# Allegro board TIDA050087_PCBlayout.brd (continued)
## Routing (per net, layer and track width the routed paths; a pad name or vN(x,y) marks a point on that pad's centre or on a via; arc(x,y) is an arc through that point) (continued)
LVDS_TX1_N: length 28.3
  TOP w0.081: 49.6,46.87 49.61,46.86 49.61,46.86 49.67,46.81 49.67,46.8 49.75,46.72 49.75,44.59 49.19,44.04 49.19,43.72 U101.A4
  TOP w0.086: v1(47.04,60.36) 47.16,60.36 47.84,59.68 47.84,58.24 46.02,56.42 43,56.42 42.18,55.6 42.18,51.54 43.04,50.68 45.79,50.68 49.6,46.87
  BOTTOM w0.086: v1(47.04,60.36) 47.09,60.36 47.88,59.57 J802.24
LVDS_TX1_P: length 28.1
  TOP w0.081: U101.B4 48.97,43.45 48.97,44.13 49.53,44.68 49.53,46.63 49.44,46.71
  TOP w0.086: 49.44,46.71 45.7,50.45 42.94,50.45 41.95,51.44 41.95,55.7 42.9,56.65 45.93,56.65 47.62,58.34 47.62,58.56 47.38,58.8 47.38,59.07 47.62,59.31 47.62,59.58 47.28,59.92 47.16,59.92 v1(47.07,59.83)
  BOTTOM w0.086: v1(47.07,59.83) 47.3,59.83 47.65,59.47 47.65,59.1 47.48,58.93 J802.22
LVDS_TX2_N: length 28
  TOP w0.081: U101.A2 48.22,44.03 48.06,44.19 48.06,44.19 48.05,44.2
  TOP w0.086: 48.05,44.2 47.69,44.57 47.69,45.89 48.01,46.21 48.01,46.7 45.43,49.27 42.28,49.27 40.89,50.66 40.89,57.19 41.43,57.73 44.97,57.73 45.32,58.09 45.32,59.74 v1(44.7,60.36)
  BOTTOM w0.086: v1(44.7,60.36) 45.48,59.58 J802.12
LVDS_TX2_P: length 28
  TOP w0.081: 47.89,44.04 47.97,43.96 47.97,43.45 U101.B2
  TOP w0.086: 47.89,44.04 47.46,44.47 47.46,45.98 47.78,46.3 47.78,46.6 45.34,49.04 42.18,49.04 40.66,50.57 40.66,57.28 41.34,57.96 44.87,57.96 45.1,58.18 45.1,58.55 44.84,58.8 44.84,58.93 45.1,59.18 45.1,59.64 44.91,59.83 v1(44.67,59.83)
  BOTTOM w0.086: v1(44.67,59.83) 44.91,59.83 45.25,59.49 45.25,59.1 45.08,58.93 J802.10
LVDS_TX3_N: length 28
  TOP w0.081: 46.66,46.62 47.21,46.08 47.21,44.42 46.97,44.18 46.97,43.94 47.56,43.34 47.58,43.34 U101.B1
  TOP w0.086: 46.66,46.62 46.66,47.13 45.17,48.63 41.98,48.63 40.21,50.4 40.21,57.46 41.12,58.38 43.73,58.38 44.22,58.86 44.22,59.62 43.52,60.32 43.51,60.32 v1(43.45,60.38)
  BOTTOM w0.086: v1(43.45,60.38) 43.46,60.38 44.28,59.56 J802.6
LVDS_TX3_P: length 27.9
  TOP w0.081: U101.C1 47.34,43.08 47.34,43.25 46.75,43.84 46.75,44.28 46.98,44.52 46.98,45.98 46.57,46.4 46.57,46.4 46.52,46.45 46.43,46.53 46.43,46.6 46.43,46.61 46.43,46.62
  TOP w0.086: v1(43.49,59.83) 43.68,59.83 43.68,59.83 43.99,59.53 43.99,58.96 43.64,58.61 43.52,58.61 43.29,58.84 43.17,58.84 42.93,58.61 42.81,58.61 42.58,58.84 42.46,58.84 42.22,58.6 41.03,58.6 39.98,57.56 39.98,50.3 41.89,48.4 45.07,48.4 46.43,47.04 46.43,46.62
  BOTTOM w0.086: v1(43.49,59.83) 43.69,59.83 44.05,59.47 44.05,59.11 43.88,58.94 J802.4
M1_SCL: length 1.5
  TOP w0.203: R906.1 2.77,39.49 U902.4
M1_SDA: length 2.1
  TOP w0.254: U902.5 5.23,38.23 4.34,37.33 R910.1
M2_SCL: length 1.5
  TOP w0.203: R926.1 2.86,52.51 U904.4
M2_SDA: length 2.2
  TOP w0.254: U904.5 5.13,50.55 R928.1
M3_SCL: length 1.4
  TOP w0.254: U907.4 17.29,39.29 R946.1
M3_SDA: length 2.2
  TOP w0.254: R948.1 18.34,37.98 U907.5
M4_SCL: length 1.7
  TOP w0.254: R988.1 3.09,26.53 U911.4
M5_SCL: length 1.5
  TOP w0.254: R1019.1 3.62,13.07 3.64,13.08 U912.4
M5_SDA: length 2.4
  TOP w0.254: U912.5 5.48,11.45 4.61,10.58 R1021.1
MX_POR_B: length 13.4
  TOP w0.112: v1(56.3,54.13) 56.38,54.05 TP408.1 56.39,53.11 56.39,45.58 55.24,44.43 55.24,43.71 U101.A16
  BOTTOM w0.112: v1(56.3,54.13) 56.3,54.08 55.84,53.62 R404.2 55.84,53.59 C405.1 54.72,53.61 R406.2
NVCC_1P8: length 13.7
  TOP w0.203: R106.1 14.08,8.19 14.08,9.27 13.22,10.12 13.22,12.01 12.83,12.4 12.15,12.4 R1029.1 ; U101.W8 50.81,34.7 v1(50.74,34.63) ; U101.R12 52.73,36.7 52.72,36.69 v1(52.72,36.69) 52.71,36.7 U101.R10
  TOP w0.381: v1(12.63,7.01) 13.2,7.01 13.47,6.74 13.53,6.8 13.53,7.62 13.95,8.04 R106.1 ; v1(46.27,28.64) v1(46.27,25.86)
  BOTTOM w0.254: C116.1 50.75,34.62 v1(50.74,34.63) ; v1(52.72,36.69) 52.77,36.63 C117.1
  vias: v1(12.41,33.78) v1(12.41,33.14) v1(12.62,7.54) v1(12.66,8.11) v1(16.28,33.78) v1(16.32,33.25)
NVCC_3P3: length 121.4
  TOP w0.203: R989.1 v1(7.35,32.59)
  TOP w0.381: 40.87,3.61 40.87,3.49 43.66,0.7 64.81,0.7 68.35,4.24 68.35,15.28 70.83,17.75 70.83,24.81 70.42,25.22 69.12,25.22 68.82,25.52 R112.2 68.13,25.82 68.13,25.81 R113.2
  L3_INT_1 w0.203: v1(7.35,32.59) 7.35,32.11 8.41,31.05 8.41,26.31 6.64,24.53 6.64,17.61 8.31,15.93 8.31,11.39 6.58,9.66 6.58,7.41 8.42,5.57 10.46,5.57 14.42,1.6 38.09,1.6 39.41,2.92 39.99,2.92 40.19,3.12 v1(40.19,3.79)
NVCC_AON: length 58.5
  TOP w0.254: TP608.1 61.64,43.19 v1(62.4,43.95) 62.4,43.96 62.84,44.4 R601.1 ; U101.L16 55.22,38.23 v1(55.2,38.2) ; R602.1 67.16,44.41 67.48,44.09 68.82,44.09 R603.1 70.43,43.54 R604.1 70.45,44.23 70.92,44.7 71.92,44.7 72.32,44.3 72.32,28.42 70.55,26.64 C804.1 69.58,25.82 R112.1
  TOP w0.305: v1(68.34,48.25) R309.1 69.4,47.51 R308.1 70.63,47.51 R306.1 71.69,47.52 R307.1 71.96,47.54 72.27,47.23 72.27,45.04 71.92,44.7
  TOP w0.381: R112.1 70.15,25.82 v1(70.18,25.84)
  L3_INT_1 w0.305: v1(68.34,48.25) 68.34,46.79 66.59,45.04 63.49,45.04 v1(62.4,43.95)
  BOTTOM w0.254: J803.90 v1(70.18,25.84) ; v1(55.2,38.2) 55.2,37.97 55.46,37.7 57.08,37.7 C119.1 57.88,37.87 61.51,41.5 61.51,43.06 v1(62.4,43.95)
NVCC_BBSM_1P8: length 157.2
  TOP w0.112: v1(19.74,16.16) 19.33,16.16 R101.2
  TOP w0.203: v1(12.1,41.63) 11.92,41.63 R903.1 ; R918.1 11.84,38.93 v1(12.12,38.93) ; v1(53.71,40.68) 53.69,40.7 U101.G12
  L3_INT_1 w0.508: v1(17.28,12.81) 12.63,17.46 12.63,26.45 13.14,26.96 13.14,54.03 13.8,54.69 18.52,54.69 19.79,53.43 v3(19.79,53.35)
  BOTTOM w0.203: v1(17.28,12.81) 17.07,12.81 16.62,13.26 16.62,15.91 10.6,21.93 10.6,38.26 11.35,39.02 12.03,39.02 v1(12.12,38.93) ; C101.1 53.26,40.88 53.36,40.98 53.36,43.06 ; v1(12.1,41.63) 12.16,41.63 12.91,40.88 12.91,38.08 11.57,36.74 11.57,23.3 14.71,20.15 17.13,20.15 20.2,17.08 20.2,16.52 19.84,16.16 v1(19.74,16.16)
  BOTTOM w0.254: v1(53.71,40.68) 53.69,40.69 C101.1
  BOTTOM w0.305: 53.32,43.33 53.36,43.28 53.36,43.06
  BOTTOM w0.508: 53.32,43.33 53.32,43.6 53.33,43.61 53.33,44.54 53.32,44.55 53.32,45.38 48.79,49.92 24.95,49.92 22.35,52.51 20.63,52.51 v3(19.79,53.35)
NVCC_BBSM_1V8: length 101.8
  TOP w0.203: R902.1 11.73,41.08 v1(12.1,41.08)
  TOP w0.381: v1(27.64,56.39) 27.9,56.13 R971.1 ; Q901.1 v1(28.13,58.28)
  L3_INT_1 w0.381: v1(53.64,52.17) 53.09,52.17 52.49,52.76 v1(52.49,52.87)
  BOTTOM w0.203: v1(19.61,18.4) 19.61,19.73 21.52,21.64 R1096.1 R1097.1 25.67,21.64 27.67,19.64 30.24,19.64 30.7,20.1 R1064.1 30.7,21.08 31.01,21.39 32.61,21.39 34.03,19.97 35.64,19.97 38.49,17.13 38.49,15.53 35.06,12.1 34.16,12.1 R1102.1 33.91,11.39 33.63,11.11 31.1,11.11 30.06,10.07 R703.1 ; J802.53 53.88,54.78 C809.1 ; v1(19.77,16.72) 19.77,17 16.95,19.82 14.58,19.82 11.24,23.16 11.24,36.88 12.56,38.21 12.56,40.76 12.24,41.08 v1(12.1,41.08)
  BOTTOM w0.254: C809.1 53.53,54.72 53.17,54.37 53.17,54.13 52.49,53.45 v1(52.49,52.87)
  BOTTOM w0.381: R405.1 57.99,52.83 57.98,52.85 R401.1 56.38,52.85 56.37,52.84 R404.1 55.17,52.17 v1(53.64,52.17) 52.49,51.02 34.3,51.02 v1(34,50.72)
NVCC_BBSM_PULL UP: length 5.9
  TOP w0.127: v1(27.31,13.42) 27.37,13.48 U701.28
  BOTTOM w0.203: R703.2 28.65,10.76 R706.1 27.31,11.37 v1(27.31,13.42)
NVCC_GPIO: length 21.6
  TOP w0.254: v1(55.18,37.22) 55.22,37.27 U101.N16 U101.N15
  TOP w0.305: v1(65.92,25.92) 65.92,26.04 65.73,26.23 C806.1
  TOP w0.381: R113.1 66.15,25.81 66.05,25.92 v1(65.92,25.92)
  BOTTOM w0.254: v1(65.92,25.92) 66.25,25.92 66.32,25.84 66.8,25.84 ; C118.1 55.44,36.7 55.18,36.97 v1(55.18,37.22)
  BOTTOM w0.381: 64.62,25.84 64.69,25.92 v1(65.92,25.92) ; 64.61,25.83 62.55,27.88 62.55,32.26 58.12,36.7 C118.1
NVCC_SD: length 50.6
  TOP w0.203: R929.1 7.5,47.87 9.48,47.87 12.89,44.46 12.89,37.67 11.31,36.08 11.31,31.86 13.29,29.88 13.29,27.12 16.44,23.97 21.15,23.97 22.36,25.18 25.33,25.18 25.86,24.65 25.86,24.29 25.9,24.29
  TOP w0.254: 30.1,18.73 29.85,18.47 U701.7
  TOP w0.305: v1(32.19,22.59) 32.19,22.28 32.52,21.95 TP713.1 32.16,21.5 31.17,21.5 30.62,20.94 C731.1 30.62,20.2 30.75,20.07 30.75,19.37 30.1,18.73
  L3_INT_1 w0.381: v1(29.22,23.68) 31.1,23.68 v1(32.19,22.59)
NVCC_SD2: length 109.1
  TOP w0.203: 24.6,24.29 24.64,24.33 24.57,24.41 24.55,24.41 24.11,24.85 22.54,24.85 21.33,23.64 16.3,23.64 12.96,26.98 12.96,29.74 10.98,31.73 10.98,36.22 12.56,37.8 12.56,44.32 9.34,47.54 6.75,47.54 R935.1
  TOP w0.254: U101.R16 v1(54.73,36.7)
  TOP w0.457: R312.1 60.74,28.29 v1(60.77,28.32) ; v1(24.06,23.12) R108.1
  L3_INT_1 w0.457: v1(67.82,31.66) 66.98,32.5 63.09,32.5 v1(61.9,31.3) ; v1(44.41,23.93) 40.19,23.93 39.33,23.08 v1(37.25,23.08)
  BOTTOM w0.254: v1(67.82,31.66) 67.82,32.13 67.3,32.64 J803.55 ; C129.1 55.23,34.29 55.23,36.39 54.93,36.7 v1(54.73,36.7)
  BOTTOM w0.305: C129.1 55.32,33.55 56.78,32.08 56.78,30.32 58.78,28.32 v1(60.77,28.32)
  BOTTOM w0.457: v1(37.25,23.08) 36.22,22.05 33.91,22.05 31.37,24.59 26.96,24.59 25.48,23.12 v1(24.06,23.12) ; v1(60.77,28.32) 61.9,29.44 v1(61.9,31.3)
  BOTTOM w0.508: v1(60.77,28.32) 60.77,26.61 59.66,25.49 51.91,25.49 49.5,23.08 45.26,23.08 v1(44.41,23.93)
ODT_CA_A: length 2.1
  TOP w0.081: v1(38.41,41.43) 38.41,41.35 U201.G2
  BOTTOM w0.081: v1(38.41,41.43) 38.31,41.53 38.31,42.67 38.18,42.8
  BOTTOM w0.104: R210.2 38.18,42.8
ONOFF: length 14.1
  TOP w0.112: v1(59.07,53.58) 59.12,53.54 TP401.1 59.32,52.25 59.32,47.97 57.82,46.47 57.82,44.97 56.72,43.88 U101.A19
  BOTTOM w0.112: v1(59.07,53.58) R405.2 58.51,54.16 58.64,54.29 58.64,55.08 58.28,55.44 J802.75
PDM_CLK: length 12.5
  TOP w0.091: U101.G17 v1(55.72,40.18)
  L3_INT_1 w0.114: v1(65.9,41.05) 65.9,41.14 65.58,41.46 57.88,41.46 57.2,40.79 56.33,40.79 v1(55.72,40.18)
  BOTTOM w0.112: v1(65.9,41.05) 66.3,41.44 J803.11
PDM_DATA0: length 13.9
  TOP w0.112: U101.J17 55.72,39.24 v1(55.71,39.23)
  L3_INT_1 w0.091: v1(55.71,39.23) 56.34,39.86 65.26,39.86 66.05,40.65 v1(67.57,40.65)
  BOTTOM w0.112: v1(67.57,40.65) 67.57,40.81 67.33,41.04 J803.13
PDM_DATA1: length 11.7
  TOP w0.091: U101.G18 56.22,40.2 v1(56.23,40.19)
  L3_INT_1 w0.114: v1(56.23,40.19) 56.63,40.59 64.89,40.59 v1(65.35,41.05)
  BOTTOM w0.112: J803.15 65.66,40.64 65.37,40.94 65.37,41.04 v1(65.35,41.05)
PMIC_32K_OUT: length 60.9
  TOP w0.112: R411.1 68.87,51.16 72.7,47.33 72.7,20.85 71.63,19.77 71.63,15.81 v1(71.07,15.25)
  L3_INT_1 w0.114: v1(60.32,14.9) 60.32,12.37 59.6,11.64 v1(59.6,9.99)
  BOTTOM w0.112: v1(59.6,9.99) J801.34 ; v1(60.32,14.9) 70.71,14.9 v1(71.07,15.25)
PMIC_NINT: length 64.7
  TOP w0.112: v1(33.89,10.35) v1(33.89,9.2) ; U701.11 28.17,19.74 29.37,20.94 v1(29.37,22.74)
  L3_INT_1 w0.091: v1(29.37,22.74) 30.03,22.74 31.32,21.44 31.38,21.44 31.38,21.44 33.94,21.44 v1(34.63,20.76)
  BOTTOM w0.112: v1(34.63,20.76) 35.67,20.76 39.17,17.25 39.17,15.35 34.18,10.36 33.9,10.36 33.89,10.35 v1(33.89,10.35) ; J801.32 60,5.26 58.58,3.84 45.95,3.84 45.37,4.43 42.78,4.43 41.64,3.28 37.62,3.28 37.34,3.56 34.47,3.56 34.14,3.23 33,3.23 32.54,3.69 32.54,7.86 v1(33.89,9.2)
PMIC_ON_REQ: length 118
  TOP w0.112: U101.A17 55.72,44.24 56.87,45.38 56.87,47.93 57.48,48.55 TP407.1 57.36,50.25 57.36,53.41 v1(57.54,53.59) ; v1(61.22,55.55) 61.62,55.95 R418.1 61.62,56.86 61.87,57.11 64.77,57.11 65.18,56.7 65.18,55.63 73.01,47.81 73.01,20.06 v1(72.06,19.11)
  L3_INT_1 w0.114: v1(57.54,53.59) 58.08,53.59 60.04,55.55 v1(61.22,55.55)
  BOTTOM w0.112: v1(72.06,19.11) 69.92,16.97 45.08,16.97 43.14,15.03 39.23,15.03 39.22,15.02 39.2,15.02 33.99,9.81 31.04,9.81 30.13,8.9 28.45,8.9 27.72,9.63 26.65,9.63 25.13,11.16 R707.1 ; v1(57.54,53.59) 57.53,53.6 R401.2 56.9,54.6 56.43,55.07 56.32,55.07 55.88,55.51 J802.63
PMIC_SCLH: length 24.7
  TOP w0.112: v1(44.63,11.79) 43.06,11.79 v1(40.87,9.61)
  BOTTOM w0.112: v1(44.63,11.79) 47.43,14.59 59.02,14.59 60,13.61 J801.31 ; R724.2 40.48,10 v1(40.87,9.61)
PMIC_SCLL: length 23.7
  BOTTOM w0.112: Q903.2 42.81,11.63 R712.2 44.44,12.59 45.27,13.42 45.27,14.33 46.18,15.25 59.23,15.25 60.8,13.68 J801.27
PMIC_SDAH: length 29.7
  BOTTOM w0.112: R725.2 35.73,8.02 35.79,8.08 40.82,8.08 43.92,11.18 44.84,11.18 45.34,11.69 45.34,12 47.63,14.28 58.87,14.28 59.6,13.55 59.6,12.47 59.6,12.46 59.6,12.14 59.6,12.14 J801.33
PMIC_SDAL: length 29.8
  BOTTOM w0.112: R713.2 38.41,9.59 37.92,9.1 ; 37.92,9.1 37.92,8.93 38.13,8.72 40.8,8.72 44.3,12.22 44.73,12.22 47.33,14.83 47.34,14.83 47.45,14.94 59.09,14.94 60.4,13.64 J801.29 ; 37.92,9.1 Q902.2
PMIC_STBY_REQ: length 22
  TOP w0.081: 56.47,43.97 56.47,43.44 U101.B18
  TOP w0.112: v1(61.87,55.51) 61.95,55.59 63.84,55.59 64.55,56.3 R417.1 ; v1(58.13,54.92) 58.59,54.45 58.59,51.6 TP409.1 58.96,51.23 58.96,48.18 57.58,46.8 57.58,45.08 56.47,43.97
  L3_INT_1 w0.114: v1(61.87,55.51) 61.18,56.21 59.42,56.21 v1(58.13,54.92)
  BOTTOM w0.112: v1(58.13,54.92) 58.13,55 57.88,55.25 J802.73
POR_B: length 98.2
  TOP w0.112: Q901.2 29.42,56.44 R971.2 v1(29.11,51.79) ; v1(20.43,14.94) 20.43,15.73 20.17,15.98 20.17,16.31 20.96,17.1 v1(20.96,18.12)
  L3_INT_1 w0.114: v1(20.96,18.12) 20.96,18.47 19.86,19.57 18.01,19.57 16.39,21.19 16.39,23.57 16.64,23.82 16.64,23.82 17.28,24.46 17.28,27.38 17.82,27.92 17.82,31.06 19.91,33.15 19.91,42.95 21.95,44.98 21.95,45.88 22.38,46.31 22.98,46.31 25.98,49.31 25.98,50.86 26.91,51.79 v1(29.11,51.79)
  BOTTOM w0.112: R1059.2 21.42,20.71 20.74,20.03 20.74,18.68 20.96,18.47 v1(20.96,18.12) ; J802.57 54.68,55.18 54.72,55.14 R406.1 54.5,54.73 54.25,54.47 54.25,53.53 54,53.29 53.46,53.29 51.84,51.67 29.24,51.67 v1(29.11,51.79) ; v1(20.43,14.94) 18.85,13.37 18.85,9.15 20.63,7.37 R1098.2
S1_CPU_VDD2_DDR: length 23.6
  TOP w0.203: R937.1 11.73,52.46 12.12,52.46 13.47,51.11 13.47,38.33 18.25,33.54 18.25,32.82 17.88,32.45 17.88,32.37
S1_CPU_VDDQ_DDR: length 30.2
  TOP w0.203: R945.1 20.19,45.49 v1(20.19,45.78)
  BOTTOM w0.203: v1(20.19,45.78) 19.9,45.49 19.9,34.88 23.41,31.36 34.1,31.36 34.61,30.85 34.61,29.7 34.92,29.4 v1(35.37,29.4)
S1_NVCC_BBSM_1V8: length 31.4
  TOP w0.203: R917.1 11.88,39.47 v1(12.13,39.47)
  BOTTOM w0.203: v1(12.13,39.47) 12.01,39.35 11.22,39.35 10.27,38.4 10.27,21.78 16.29,15.76 16.29,13.24 v1(15.75,12.71)
S1_VDD_SOC_0V85: length 63.1
  TOP w0.203: R924.1 7.19,58.87 v1(7.19,59.37)
  BOTTOM w0.203: v1(7.19,59.37) 7.07,59.25 7.07,58.57 7.67,57.97 7.67,55.34 14.47,48.54 14.47,36.19 15.85,34.81 15.85,32.31 20.92,27.24 39.59,27.24 42.43,24.39 42.43,23.31 v1(42.75,22.99)
S1_VSYS_5V: length 51.6
  TOP w0.203: R983.1 11.97,28.18 12.17,28.38 v1(12.17,28.71)
  L3_INT_1 w0.203: v1(12.17,28.71) 12.32,28.56 12.32,27.41 11.74,26.83 11.74,11.67 15.27,8.14 27.49,8.14 28.17,7.45 31.6,7.45 35.36,3.69 38.13,3.69 39.61,5.17 39.61,5.65 39.82,5.85 v1(40.7,5.85)
  vias: v1(41.79,8.08) v1(42.2,8.44) v1(44.89,9.71) v1(45.01,10.24) v1(45.47,9.76) v1(45.6,10.29)
SAI1_RXD0: length 15.5
  TOP w0.081: 58.36,39.95 57.47,39.95 U101.H20
  TOP w0.112: 58.36,39.95 66.36,39.95 66.67,40.26 70.49,40.26 70.81,40.59 v1(70.84,40.59)
  BOTTOM w0.112: v1(70.84,40.59) 70.84,40.53 70.56,40.24 J803.18
SAI1_TXC: length 17.1
  TOP w0.081: 58.64,40.44 57.48,40.44 U101.G20
  TOP w0.112: v1(71.24,41.75) 71.2,41.75 70.66,41.21 70.33,41.21 70,40.88 68.88,40.88 68.46,41.3 67.04,41.3 66.16,40.43 58.65,40.43 58.64,40.44
  BOTTOM w0.112: v1(71.24,41.75) 71.24,41.66 70.63,41.04 J803.14
SAI1_TXD0: length 18.5
  TOP w0.112: 71.5,42.82 70.46,42.82 R604.2 ; 71.5,42.82 R612.1 ; 71.5,42.82 71.51,42.82 71.84,42.49 71.84,41.17 TP604.1 71.58,40.97 70.68,40.97 70.36,40.64 v1(70.31,40.64) 68.78,40.64 68.36,41.06 67.14,41.06 66.26,40.19 57.73,40.19 U101.H21
  BOTTOM w0.112: J803.16 v1(70.31,40.64)
SAI1_TXFS: length 16.7
  TOP w0.112: v1(70.71,41.81) 70.36,41.46 69.43,41.46 TP603.1 69.36,41.66 69.36,42.78 69.36,42.79 ; U101.G21 57.75,40.67 66.06,40.67 68.2,42.81 R611.1 69.33,42.81 69.36,42.79 ; 69.36,42.79 R603.2
  BOTTOM w0.112: J803.12 70.34,41.44 v1(70.71,41.81)
SD1_CLK: length 20
  TOP w0.081: U501.M6 55.26,19.75 54.37,19.75 54.12,19.49 54.06,19.49 ; U101.Y11 52.97,33.95 52.97,32.87 52.67,32.56
  TOP w0.112: 52.67,32.56 52.67,27.33 53.02,26.97 TP503.1 53.02,23.5 53.13,23.39 53.32,23.39 53.43,23.28 53.43,23.05 53.32,22.94 53.13,22.94 53.02,22.83 53.02,22.61 53.13,22.49 53.32,22.49 53.43,22.38 53.43,22.16 53.32,22.05 53.13,22.05 53.02,21.94 53.02,21.71 53.13,21.6 53.32,21.6 53.43,21.49 53.43,21.27 53.32,21.15 53.13,21.15 53.02,21.04 53.02,20.82 53.13,20.71 53.31,20.71 53.42,20.59 53.42,20.37 53.31,20.26 53.13,20.26 53.02,20.15 53.02,19.65 53.17,19.49 54.06,19.49
SD1_CMD: length 19.8
  TOP w0.081: 54.33,23.11 54.79,23.11 55.26,22.63 55.26,22.39 55.26,22.39 55.26,22.1 55.26,22.1 55.26,21.89 55.26,21.89 55.26,21.6 55.26,21.6 55.26,21.39 55.26,21.39 55.26,21.1 55.26,21.1 55.26,20.89 55.26,20.89 55.26,20.74 U501.M5 ; U101.AA12 53.22,32.87 52.9,32.55
  TOP w0.112: 52.9,32.55 52.9,27.81 53.07,27.65 53.31,27.65 53.42,27.76 53.42,28.13 53.54,28.24 54.11,28.24 54.22,28.13 R502.2 54.22,27.45 TP502.1 53.66,26.25 53.59,26.19 53.59,25.95 53.7,25.84 54.05,25.84 54.22,25.67 54.22,25.41 54.11,25.3 53.6,25.3 53.49,25.19 53.49,24.97 53.6,24.85 54.11,24.85 54.22,24.74 54.22,24.52 54.11,24.41 53.6,24.41 53.49,24.3 53.49,24.07 53.6,23.96 54.11,23.96 54.22,23.85 54.22,23.22 54.33,23.11
SD1_DATA0: length 20
  TOP w0.081: U101.AA14 54.22,32.61 54.41,32.43 54.89,32.43 55.35,31.96 55.35,31.23
  TOP w0.112: U501.A3 61.4,21.49 61.92,22.02 61.92,22.65 60.66,23.91 60.66,24.68 60.55,24.8 58.43,24.8 58.31,24.91 58.31,25.42 58.43,25.53 59.29,25.53 59.7,25.94 TP501.1 58.44,26.06 R501.2 58.4,26.32 55.35,29.36 55.35,31.23
SD1_DATA1: length 19.8
  TOP w0.081: 55.83,31.96 55.03,32.76 54.74,32.76 54.63,32.87 54.63,33.61 U101.AA15
  TOP w0.104: 55.83,31.96 55.83,31.26
  TOP w0.112: U501.A4 61.08,20.92 61.57,20.92 62.42,21.78 62.42,23.47 62.31,23.59 61.67,23.59 61.46,23.79 61.46,23.99 61.59,24.12 62.1,24.12 62.21,24.23 62.21,24.41 62.05,24.57 61.34,24.57 61.23,24.68 61.23,25.17 61.12,25.29 60.74,25.29 60.55,25.47 60.55,26.16 59.98,26.73 58.72,26.73 55.83,29.62 55.83,31.26
SD1_DATA2: length 19.8
  TOP w0.081: U101.AA16 55.28,33.64 55.28,33.53 55.17,33.42 55.02,33.42 54.96,33.36 54.96,33.19 55.05,33.11 55.18,33.11 56.31,31.98
  TOP w0.112: 56.31,31.98 56.31,29.82 58.92,27.21 60.31,27.21 61.03,26.5 61.03,25.96 61.23,25.76 61.64,25.76 61.75,25.65 61.75,25.18 61.86,25.07 62.52,25.07 62.92,24.66 62.92,24.42 62.68,24.18 62.68,23.89 62.92,23.65 62.92,21.47 61.98,20.52 61.04,20.52 U501.A5
SD1_DATA3: length 19.8
  TOP w0.081: U501.B2 60.76,22.24 61.25,22.24 61.36,22.36 61.36,22.51 ; U101.AA13 53.72,32.78
  TOP w0.112: 61.36,22.51 60.12,23.75 60.12,24.17 60.01,24.28 58.49,24.28 58.38,24.17 58.38,23.3 58.12,23.05 57.04,23.05 56.58,23.51 56.58,27.25 53.38,30.45 53.38,32.44 53.72,32.78
SD1_DATA4: length 19.9
  TOP w0.081: U101.Y13 53.97,33.95 53.97,32.75 53.62,32.4 ; U501.B3 60.76,21.75 61.18,21.75 61.67,22.24 61.67,22.42
  TOP w0.112: 53.62,32.4 53.62,30.55 56.82,27.35 56.82,24.08 56.93,23.97 57.82,23.97 57.93,24.08 57.93,24.27 58.18,24.52 60.31,24.52 60.43,24.41 60.43,23.81 61.67,22.57 61.67,22.42
SD1_DATA5: length 19.8
  TOP w0.081: U501.B4 60.76,21.24 61.5,21.24 62.02,21.77 ; 55.59,31.95 54.95,32.6 54.64,32.6 54.47,32.77 54.47,34.12 54.39,34.2 U101.Y14
  TOP w0.104: 55.59,31.23 55.59,31.95
  TOP w0.112: 62.02,21.77 62.17,21.92 62.17,22.74 60.9,24.01 60.9,24.94 60.79,25.05 59.85,25.05 59.74,25.16 59.74,25.46 59.85,25.57 60.16,25.57 60.27,25.69 60.27,26.11 59.88,26.49 58.62,26.49 55.59,29.52 55.59,31.23
SD1_DATA6: length 20
  TOP w0.081: U101.Y15 54.89,34.2 54.98,34.12 54.98,33.6 54.8,33.42 54.8,33.06 54.93,32.93 55.11,32.93 56.07,31.97 ; 61.84,20.86 61.73,20.75 60.76,20.75 U501.B5
  TOP w0.112: 56.07,31.97 56.07,29.72 58.82,26.97 60.08,26.97 60.79,26.26 60.79,25.74 61,25.52 61.22,25.52 61.47,25.27 61.47,24.92 61.58,24.81 62.15,24.81 62.45,24.51 62.45,23.79 62.67,23.57 62.67,21.69 61.84,20.86
SD1_DATA7: length 20.1
  TOP w0.076: 60.76,20.25 U501.B6
  TOP w0.081: 56.55,32 55.47,33.07 55.47,33.95 U101.Y16 ; 62.02,20.24 62.01,20.25 60.76,20.25
  TOP w0.112: 62.02,20.24 62.04,20.24 63.17,21.38 63.17,24.75 60.48,27.45 59.13,27.45 56.55,30.03 56.55,32
SD1_STROBE: length 19.9
  TOP w0.081: 56.45,23.11 56.67,22.88 56.97,22.88 57.26,22.59 57.26,21.36 57.51,21.11 U501.H5 ; 53.14,32.52 53.47,32.84 53.47,33.95 U101.Y12
  TOP w0.112: 56.45,23.11 56.08,23.47 56.08,23.97 55.97,24.09 55.51,24.09 55.4,24.2 55.4,24.42 55.51,24.53 55.97,24.53 56.08,24.64 56.08,24.87 55.97,24.98 55.51,24.98 55.4,25.09 55.4,25.31 55.51,25.43 55.97,25.43 56.08,25.54 TP505.1 56.08,27.41 54.73,28.76 54.57,28.76 54.33,28.52 54.17,28.52 54.02,28.68 54.02,28.84 54.25,29.08 54.25,29.24 54.1,29.39 53.94,29.39 53.7,29.16 53.54,29.16 53.38,29.31 53.38,29.47 53.62,29.71 53.62,29.87 53.14,30.35 53.14,32.52
SD2_CLK: length 14.3
  TOP w0.081: U101.AA19 56.72,33.37 57.63,32.46
  TOP w0.112: 57.63,32.46 57.82,32.27 57.82,30.85 59.12,29.55 63.69,29.55 63.8,29.67 63.8,30.46 63.91,30.57 64.16,30.57 64.3,30.43 64.56,30.43 64.73,30.6 65.48,30.6 65.62,30.46 v1(65.62,30.25)
  BOTTOM w0.112: J803.65 66,30.64 65.62,30.26 v1(65.62,30.25)
SD2_CMD: length 14.8
  TOP w0.081: U101.Y19 56.89,34.2 56.98,34.12 56.98,33.46 57.81,32.63
  TOP w0.112: 57.81,32.63 58.06,32.38 58.06,30.95 59.22,29.8 63.41,29.8 63.52,29.91 63.52,30.67 63.69,30.84 64.8,30.84 64.91,30.95 64.91,30.98 v1(64.93,31) 65.01,31 65.08,31.07 R311.2
  BOTTOM w0.112: v1(64.93,31) 64.99,30.94 66.32,30.94 66.42,31.04 J803.63
SD2_DATA0: length 15.1
  TOP w0.081: U101.Y18 56.47,33.95 56.47,33.22 57.43,32.26
  TOP w0.112: 57.43,32.26 57.5,32.19 57.5,30.83 59.05,29.29 63.9,29.29 64.82,30.21 65.02,30.21 v1(65.03,30.22) 65.03,30.19 65.06,30.16 R310.2
  BOTTOM w0.112: J803.69 65.28,29.84 65.03,30.09 v1(65.03,30.22)
SD2_DATA1: length 14.4
  TOP w0.081: U101.AA18 56.22,33.07 57.24,32.06
  TOP w0.112: v1(65.06,28.73) 65.03,28.73 64.73,29.03 58.97,29.03 57.26,30.74 57.26,32.03 57.24,32.06
  BOTTOM w0.112: J803.71 65.22,29.44 65.08,29.31 65.08,28.76 v1(65.06,28.73)
SD2_DATA2: length 14.3
  TOP w0.081: U101.Y20 57.48,33.94 57.48,33.59 57.95,33.11
  TOP w0.112: 57.95,33.11 59.88,33.11 61.06,31.93 61.06,31.17 61.17,31.05 61.4,31.05 61.51,31.17 61.51,31.84 61.62,31.95 62.19,31.95 62.33,31.81 62.33,31.14 62.44,31.04 62.73,31.04 62.84,31.15 62.84,31.84 62.95,31.95 64.24,31.95 v1(64.4,31.79)
  BOTTOM w0.112: v1(64.4,31.79) 64.53,31.93 65.16,31.93 65.6,31.48 66.01,31.48 66.37,31.84 J803.59
SD2_DATA3: length 14.4
  TOP w0.081: 57.59,33.22 57.22,33.59 U101.AA20
  TOP w0.112: 57.59,33.22 57.59,33.2 58.3,32.49 58.3,31.05 59.27,30.08 60.76,30.08 60.87,30.19 60.87,30.37 60.98,30.48 61.21,30.48 61.32,30.37 61.32,30.19 61.43,30.08 61.66,30.08 61.77,30.19 61.77,30.37 61.88,30.48 62.1,30.48 62.21,30.37 62.21,30.19 62.33,30.08 63.01,30.08 63.19,30.26 63.19,31.04 63.35,31.2 64.35,31.2 64.68,31.53 v1(64.96,31.53)
  BOTTOM w0.112: v1(64.96,31.53) 65.08,31.53 65.39,31.22 66.13,31.22 66.36,31.44 J803.61
SD2_NCD: length 15.4
  TOP w0.081: U101.Y17 55.97,33.95 55.97,33.07 57.02,32.02
  TOP w0.112: 57.02,32.02 57.02,30.3 58.56,28.76 64.46,28.76 64.91,28.31 65.31,28.31 65.62,28.62 v1(65.62,28.66)
  BOTTOM w0.112: v1(65.62,28.66) 66,29.04 J803.73
SD2_RESET_B: length 10.6
  TOP w0.081: U101.AA17 55.72,33.07 56.79,32.01
  TOP w0.112: 56.79,32.01 56.79,30.2 58.7,28.29 R312.2 59.44,27.9 59.54,27.81 61.41,27.81 TP972.1
SD2_VSEL: length 82.3
  TOP w0.081: U101.V18 v1(56.73,34.69)
  L3_INT_1 w0.081: 57.32,34.59 57.22,34.69 v1(56.73,34.69)
  L3_INT_1 w0.091: v1(31.65,22.08) 31.68,22.05 34.75,22.05 34.75,22.03 35.82,20.96 42.35,20.96 43.97,19.34 45.88,19.34 46.26,18.96 46.26,16.76 v1(45.92,16.42)
  L3_INT_1 w0.114: 57.32,34.59 71.28,34.59 v1(71.79,35.1)
  BOTTOM w0.112: R1083.2 29.47,20.39 R1100.1 29.62,21.19 29.93,21.19 30.82,22.08 v1(31.65,22.08) ; v1(71.79,35.1) 72.44,34.45 72.44,18.69 69.91,16.16 46.17,16.16 v1(45.92,16.42)
SD3_CLK: length 23.6
  TOP w0.081: U101.V16 55.79,35.2 v1(55.79,35.19)
  L3_INT_1 w0.081: 56.18,34.16 56.16,34.18 56.16,34.82 v1(55.79,35.19)
  L3_INT_1 w0.114: v1(70.75,31.86) 70.73,31.88 70.73,31.89 70.34,32.27 69.09,32.27 68.99,32.17 68.99,32.11 68.87,32 68.52,32 68.41,32.11 68.41,32.27 67.62,33.06 62.53,33.06 61.71,33.88 61.46,33.88 61.37,33.79 61.37,33.19 61.28,33.1 61.1,33.1 61.01,33.19 61.01,33.79 60.91,33.88 60.73,33.88 60.64,33.79 60.64,33.19 60.55,33.1 60.37,33.1 60.27,33.19 60.27,33.79 60.18,33.88 59.65,33.88 59.56,33.79 59.56,32.99 59.46,32.9 59.28,32.9 59.19,32.99 59.19,33.79 59.1,33.88 56.47,33.88 56.18,34.16
  BOTTOM w0.112: J803.62 70.51,31.44 70.75,31.69 v1(70.75,31.86)
SD3_CMD: length 23.6
  TOP w0.081: U101.U16 55.66,35.7 v1(55.72,35.76)
  L3_INT_1 w0.081: 56.67,34.29 56.35,34.61 56.35,35.13 v1(55.72,35.76)
  L3_INT_1 w0.114: v1(71.28,31.85) 71.28,31.9 70.66,32.52 68.71,32.52 67.85,33.38 64.94,33.38 64.85,33.47 64.85,33.94 64.76,34.03 64.58,34.03 64.49,33.94 64.49,33.47 64.39,33.38 64.21,33.38 64.12,33.47 64.12,33.94 64.03,34.03 63.85,34.03 63.75,33.94 63.75,33.47 63.66,33.38 63.48,33.38 63.39,33.47 63.39,33.94 63.3,34.03 63.11,34.03 63.02,33.94 63.02,33.47 62.93,33.38 62.6,33.38 62.36,33.62 62.36,34.05 62.12,34.29 56.67,34.29
  BOTTOM w0.112: J803.64 70.48,31.04 71.28,31.85 v1(71.28,31.85)
SD3_DATA0: length 23.2
  TOP w0.081: U101.T16 54.77,36.2 v1(54.75,36.18)
  L3_INT_1 w0.114: v1(71.18,30.94) 71.13,30.9 69.56,30.9 69.44,31.02 69.44,31.33 69.32,31.45 68.86,31.45 68.75,31.33 68.75,31.08 68.57,30.9 65.53,30.9 65.24,30.61 61.17,30.61 60.76,30.2 59.07,30.2 55.33,33.94 55.33,35.59 v1(54.75,36.18)
  BOTTOM w0.112: J803.66 70.88,30.64 v1(71.18,30.94)
SD3_DATA1: length 23.6
  TOP w0.081: U101.V14 54.72,35.2 v1(54.74,35.17)
  L3_INT_1 w0.114: v1(54.74,35.17) 55.11,34.81 55.11,33.57 58.96,29.72 62.46,29.72 62.57,29.83 62.57,29.98 62.69,30.09 62.91,30.09 63.03,29.98 63.03,29.83 63.14,29.72 63.37,29.72 63.49,29.83 63.49,29.91 63.6,30.02 63.83,30.02 63.94,29.91 63.94,29.83 64.06,29.72 68.08,29.72 68.17,29.81 68.17,30.12 68.26,30.21 68.44,30.21 68.54,30.12 68.54,29.81 68.63,29.71 68.81,29.71 68.9,29.81 68.9,30.12 68.99,30.21 69.18,30.21 69.27,30.12 69.27,29.77 69.36,29.68 70.24,29.68 70.71,30.16 v1(70.71,30.22)
  BOTTOM w0.112: v1(70.71,30.22) 70.71,30.07 70.49,29.84 J803.70
SD3_DATA2: length 22.4
  TOP w0.081: v1(54.68,35.68) 54.65,35.7 U101.U14
  L3_INT_1 w0.114: v1(54.68,35.68) 54.36,35.36 54.36,33.89 58.82,29.43 71.04,29.43 v1(71.05,29.44)
  BOTTOM w0.112: J803.72 v1(71.05,29.44)
SD3_DATA3: length 23.7
  TOP w0.081: v1(53.72,36.18) 53.74,36.2 U101.T14
  L3_INT_1 w0.114: v1(70.71,28.65) 70.71,28.95 70.51,29.16 58.54,29.16 54.12,33.58 54.12,35.51 54.23,35.62 54.23,35.83 53.88,36.18 v1(53.72,36.18)
  BOTTOM w0.112: J803.74 70.46,29.04 70.71,28.78 v1(70.71,28.65)
SYS_NRST: length 106.4
  TOP w0.112: TP915.1 27.31,9.56 27.31,9.85 v1(27.51,10.05)
  L3_INT_1 w0.114: v1(18.19,53.16) 17.84,53.5 15.35,53.5 14.46,52.61 14.46,37.09 16.74,34.81 16.74,28.22 14.31,25.79 14.31,18.57 15.12,17.76 15.12,16.97 18.52,13.57 18.52,9.81 18.9,9.43 26.89,9.43 v1(27.51,10.05)
  BOTTOM w0.112: v1(27.51,10.05) 27.74,10.05 R706.2 ; J802.77 58.68,56.91 58.12,57.47 54.87,57.47 54.71,57.31 42.01,57.31 37.33,52.64 29.29,52.64 28.34,53.59 21.69,53.59 21.09,54.2 19.33,54.2 18.29,53.16 v1(18.19,53.16)
TAMPER0: length 14.2
  TOP w0.081: 55.76,44.62 55.47,44.33 55.47,43.45 U101.B16
  TOP w0.112: 55.76,44.62 56.63,45.48 56.63,49.3 56.78,49.45 56.78,51.91 TP410.1 56.9,52.03 56.9,54.41 56.62,54.69 v1(56.27,54.69)
  BOTTOM w0.112: v1(56.27,54.69) 56.27,54.73 55.48,55.52 J802.61
TAMPER1: length 20.9
  TOP w0.091: v1(54.76,41.17) 54.73,41.2 U101.F14
  TOP w0.112: TP411.1 56.96,57.17 v1(56.96,56.98)
  L3_INT_1 w0.114: v1(56.96,56.98) 56.96,56.08 55.55,54.67 55.55,43.27 55.31,43.03 55.31,41.68 54.83,41.2 54.78,41.2 v1(54.76,41.17)
  BOTTOM w0.112: J802.59 55.08,56.74 55.56,57.22 56.72,57.22 v1(56.96,56.98)
TEMP_NINT: length 3.4
  TOP w0.203: TP908.1 5.37,3.45 4.48,3.45 R1009.2 3.34,4.59 U913.3
TPS65219_GPIO1: length 27.1
  TOP w0.112: U919.4 26.83,7.38 27.03,7.17 v1(27.44,7.17) 27.59,7.33 27.59,8.29 v1(28.61,9.3)
  BOTTOM w0.112: v1(28.61,9.3) 29.9,9.3 31.4,10.8 34.16,10.8 38.84,15.48 38.84,17.23 35.79,20.28 34.31,20.28 R1094.1 ; R1095.1 26.82,7.17 v1(27.44,7.17)
UART1_RXD: length 11.2
  TOP w0.081: 58.32,41.44 57.48,41.44 U101.E20
  TOP w0.112: TP612.1 63.82,41.92 v1(63.78,41.88) 63.32,41.42 58.34,41.42 58.32,41.44
  BOTTOM w0.112: v1(63.78,41.88) 64.95,43.04 J803.3
UART1_TXD: length 13.2
  TOP w0.112: U101.E21 57.76,41.66 62.98,41.66 v1(63.17,41.85) 63.17,42.22 TP610.1 62.73,43.33 R601.2 63.67,43.65 63.75,43.57 R609.1
  BOTTOM w0.112: J803.1 64.63,43.44 63.17,41.99 v1(63.17,41.85)
UART2_RXD: length 11.2
  TOP w0.081: U101.F20 57.47,40.95 58.38,40.95
  TOP w0.112: TP616.1 66,42.43 65.54,41.97 v1(65.42,41.97) 64.4,40.95 58.38,40.95
  BOTTOM w0.112: J803.7 65.99,42.24 65.72,41.97 v1(65.42,41.97)
UART2_TXD: length 13.4
  TOP w0.112: U101.F21 57.74,41.18 64.21,41.18 64.72,41.7 v1(64.72,41.85) 64.72,41.93 64.84,42.05 64.84,42.6 TP614.1 64.91,43.25 65.24,43.57 R610.1 66.24,43.57 66.32,43.66 R602.2
  BOTTOM w0.112: v1(64.72,41.85) 64.72,41.93 64.84,42.05 64.84,42.21 65.28,42.64 J803.5
USB1_DN: length 19.4
  TOP w0.102: U101.A14 54.22,43.87 54.34,43.98 54.34,44.8 55.37,45.83 55.37,52.39 54.95,52.81 54.95,54.55 53.5,56 53.5,56.39 TP611.1 52.68,57.28 53.24,57.84 53.24,59.54 v1(52.96,59.82)
  BOTTOM w0.102: v1(52.96,59.82) 53.26,59.53 53.26,59.13 53.08,58.95 J802.50
USB1_DP: length 19.5
  TOP w0.081: U101.B14 54.47,43.44 54.47,43.81
  TOP w0.102: 54.47,43.81 54.55,43.89 54.55,44.71 55.58,45.74 55.58,52.48 55.16,52.9 55.16,54.64 53.73,56.08 53.73,56.59 53.95,56.82 TP613.1 53.95,57.34 53.48,57.82 53.48,59.71 v1(53.58,59.81)
  BOTTOM w0.102: J802.52 53.48,59.71 v1(53.58,59.81)
USB1_ID: length 22.8
  TOP w0.081: U101.C11 52.47,42.95 52.11,42.95 51.97,43.08 51.97,43.8 52.07,43.89 52.07,44.29 52.33,44.55 52.33,44.62
  TOP w0.112: v1(49.53,53.02) 49.53,52.88 52.33,50.07 52.33,44.62
  L3_INT_1 w0.114: v1(49.51,57.76) 49.98,57.29 49.98,53.48 v1(49.53,53.02)
  BOTTOM w0.112: J802.56 54.28,58.2 53.68,57.59 49.68,57.59 v1(49.51,57.76)
USB1_RXN: length 21.3
  TOP w0.102: v1(49.61,60) 49.61,59.94 49.98,59.57 49.98,59.25 49.78,59.05 49.78,58.85 49.97,58.66 49.97,58.52 49.79,58.34 49.79,58.19 49.98,58 49.98,56.22 50.56,55.64 52.09,55.64 52.92,54.81 52.92,52.03 54.05,50.91 54.05,45.77 53.45,45.17 53.45,44.22 53.22,44 U101.A12
  BOTTOM w0.102: J802.34 49.88,58.95 50.01,59.08 50.01,59.6 v1(49.61,60)
USB1_RXP: length 21.3
  TOP w0.076: 53.47,43.94 53.47,43.44 U101.B12
  TOP w0.102: v1(50.14,60) 50.14,60 50.14,59.71 50.19,59.66 50.19,56.31 50.65,55.86 52.18,55.86 53.14,54.9 53.14,52.12 54.26,51 54.26,45.68 53.67,45.08 53.67,44.13 53.47,43.94
  BOTTOM w0.102: v1(50.14,60) 50.23,59.92 50.23,59.2 50.28,59.15 J802.36
USB1_TXN: length 21.6
  TOP w0.102: U101.A13 53.72,43.93 53.89,44.1 53.89,44.99 54.69,45.79 54.69,51.7 54.36,52.04 54.36,54.28 52.44,56.2 51.19,56.2 50.5,56.89 50.5,57.82 50.8,58.12 50.8,58.42 50.59,58.62 50.59,58.94 50.7,59.04 50.96,59.04 51.06,59.14 51.06,59.68 50.7,60.04 v1(50.68,60.04)
  BOTTOM w0.102: v1(50.68,60.04) 51.2,59.51 51.2,59.08 51.14,59.02 51.14,58.71 J802.40
USB1_TXP: length 21.6
  TOP w0.081: 53.98,43.88 53.98,43.45 U101.B13
  TOP w0.102: 53.98,43.88 54.11,44.01 54.11,44.9 54.91,45.7 54.91,51.79 54.57,52.13 54.57,54.37 52.53,56.42 51.28,56.42 50.72,56.98 50.72,57.73 51.01,58.03 51.01,58.78 51.28,59.05 51.28,59.77 51.17,59.88 51.17,60.02 v1(51.21,60.07)
  BOTTOM w0.102: v1(51.21,60.07) 51.21,60.07 51.39,59.64 51.48,59.41 J802.42
USB1_VBUS: length 1.5
  TOP w0.112: R613.1 51.37,58.36 51.37,57.25 TP609.1
USB1_VBUS_3V3: length 5.6
  TOP w0.203: v1(52.37,57.99) 52.34,58.02 R613.2 52.34,58.72 52.21,58.85 52.21,59.32 R301.2 52.18,59.86 52.76,60.44 54.37,60.44 54.57,60.24 R614.1
  BOTTOM w0.203: v1(52.37,57.99) 52.28,58.08 J802.46
USB2_DN: length 18.9
  TOP w0.102: 54.78,44.61 54.78,43.75 U101.A15
  TOP w0.104: 54.78,44.61 55.37,45.2 55.87,45.7 55.87,52.68 55.55,53.01 55.55,56.65 55.85,56.95 55.85,57.81 55.75,57.91 55.55,57.91 55.55,57.9 55.41,58.04 55.41,58.26 55.55,58.4 55.55,58.69 55.41,58.83 55.41,59.04 55.55,59.18 55.55,59.57 55.38,59.74 v1(55.38,59.89)
  BOTTOM w0.102: J802.62 55.48,58.96 55.64,59.13 55.64,59.63 v1(55.38,59.89)
USB2_DP: length 18.9
  TOP w0.076: U101.B15 54.97,43.45 54.97,44.49 55.01,44.53
  TOP w0.104: 55.01,44.53 56.09,45.61 56.09,52.77 55.77,53.1 55.77,56.56 56.07,56.86 56.07,57.9 55.84,58.13 55.84,58.15 55.77,58.22 55.77,59.6 v1(55.99,59.83)
  BOTTOM w0.102: v1(55.99,59.83) 55.88,59.71 J802.64
USB2_ID: length 20.4
  TOP w0.091: v1(53.79,41.71) 53.73,41.71 53.71,41.7 U101.E12
  L3_INT_1 w0.114: v1(53.79,41.71) 53.79,41.71 53.87,41.71 54.21,42.05 54.21,46.78 54.84,47.41 54.84,55.57 54.07,56.34 54.07,57.35 v1(54.62,57.89)
  BOTTOM w0.112: v1(54.62,57.89) 54.65,57.86 56.29,57.86 56.68,58.25 J802.68
USB2_VBUS_3V3: length 0.8
  BOTTOM w0.112: R304.2 54.59,59.38 54.68,59.29 J802.58
VLDO3_1V8: length 24.6
  TOP w0.254: C729.1 24.05,17.58 24.31,17.58 24.63,17.27 U701.21
  TOP w0.305: 23.13,17.06 23.61,17.06 23.95,17.41 C729.1
  TOP w0.381: 23.13,17.06 v1(21.51,17.06)
  TOP w0.508: TP711.1 13.92,2.93 R111.1 13.57,2.93 13.57,3.39 14.08,3.89 v1(14.31,3.89)
  BOTTOM w0.508: 17.86,11.44 17.86,14.97 18.37,15.48 19.92,15.48 v1(21.51,17.06)
  BOTTOM w0.762: 17.86,11.44 17.86,9.58 14.31,6.03 v1(14.31,3.89)
VLS_3V3: length 95.7
  TOP w0.203: U910.4 38.02,25.57 37.82,25.37 37.46,25.37 37.08,24.99 C935.1 ; U903.4 14.47,17.77 15.25,18.55 15.25,19.33 C909.1 ; C912.1 16.52,19.21 v1(16.52,18.8) ; U908.4 19.35,27.44 18.58,26.67 C931.1
  TOP w0.254: R922.2 14.27,19.39 15.24,19.39 C909.1 ; U906.4 44.93,15.87 C922.1 ; C901.1 45.95,6.1 45.98,6.12 U901.3
  TOP w0.305: C922.1 C923.1 45,12.73 45.4,12.33 v1(46.44,12.33)
  TOP w0.381: C912.1 15.29,19.37 C909.1 ; v1(46.45,6.02) C901.1 45.22,6.02 C906.1 ; R951.2 19.65,24.57 18.92,25.31 C931.1 17.5,25.31 C930.1 17.47,25.33 v1(16.74,25.33) ; v1(46.44,12.33) R938.2 46.44,23.55 45.32,24.67 41.46,24.67 40.75,23.96 R985.2 38.24,23.96 37.49,24.71 C935.1 35.98,24.71 C938.1 35.98,24.71 v1(35.25,24.71)
  TOP w0.457: v1(52.56,5.22) 52.57,5.23 52.57,6.14 D902.1 D901.1 56.19,7.98 TP903.1
  L3_INT_1 w0.381: v1(16.74,25.33) 16.69,25.33 16.54,25.18 16.51,25.18 15.83,24.5 15.83,19.49 v1(16.52,18.8)
  BOTTOM w0.381: v1(35.25,24.71) 34.78,25.18 16.9,25.18 v1(16.74,25.33) ; v1(46.45,6.02) 47.26,5.21 48.06,5.21 R907.2 v1(52.56,5.22) 52.56,6.31 51.9,6.97 49.99,6.97 46.44,10.52 v1(46.44,12.33)
VMEAS_3V3: length 117.5
  TOP w0.254: U911.2 3.03,27.83 C937.1 ; U904.2 2.81,53.81 C913.1 ; U913.8 2.34,9.08 C943.1 ; U912.2 3.16,14.39 C947.1 ; 2.75,9.11 2.88,9.24 C944.1 3.3,9.22 3.3,8.75 v1(3.24,8.69) ; U907.2 15.49,40.64 C925.1 ; U912.15 6.13,17.72 C946.1 ; U902.2 2.59,40.79 C904.1 ; U911.15 6.11,31.05 5.88,31.28 C934.1 ; U909.12 23.56,51.98 23.95,52.37 ; U904.15 5.78,57.3 C911.1 ; U902.15 5.88,44.44 C903.1 ; U907.15 18.99,43.74 C926.1
  TOP w0.381: R952.1 27.25,53.33 v1(27.44,53.14) ; v1(27.34,49.1) 27.11,49.33 R1037.1 ; v1(21.09,55.63) 21.09,55.63 R953.1 ; R956.2 14.74,43.36 v1(14.99,43.62) ; R959.2 v1(17.7,45.22) ; v1(15.45,39.97) 15.49,40.01 C925.1 ; R1011.1 v1(32.11,51.05) v1(33.27,51.05) 33.78,51.55 C942.1 R1013.1 36.77,50.33 U914.6 34.67,50.33 34.29,49.95 34.29,47.58 34.69,47.18 R1012.1 ; C934.1 5.39,31.84 4.65,32.58 R995.2 v1(3.48,32.58) ; v1(20.84,46.73) R977.1 ; TP902.1 v1(33.52,58.89) ; 32.91,54.46 32.88,54.49 C916.1 32.24,56.45 v1(32.24,56.46) ; 32.91,54.46 v1(32.18,54.46) ; 32.91,54.46 C915.1 ; R934.2 v1(2.02,56.7) ; v1(2.8,9.11) C943.1 ; R1009.1 v1(5.13,2.71) ; v1(3.03,27.15) C937.1 ; R914.2 v1(1.81,43.66) ; v1(4.69,44.94) C903.1 ; v1(3.1,13.68) C947.1 ; C913.1 2.77,53.31 v1(2.71,53.25) ; v1(22.78,46.76) R976.1 ; v1(2.57,40.16) C904.1 ; v1(27.26,51.38) R1036.1 ; v1(4.14,59.25) 3.92,59.03 R936.2 ; v1(17.71,44.41) C926.1 ; 23.95,52.37 24.36,52.78 C929.1 C928.1 25.6,54.07 25.06,53.53 25.06,53.3 v1(24.89,53.13) ; D902.2 50.59,5.97 v1(50.59,4.66) ; R915.2 v1(3.29,45.69) ; v1(4.64,57.82) C911.1 ; R1025.2 v1(2.34,17.21) ; v1(26.27,46.69) 26.27,46.98 R975.1 ; v1(3.92,18.82) R1027.2 4.91,18.82 5.23,18.5 5.23,18.33 5.51,18.05 C946.1 ; R994.2 v1(2.27,30.62)
  L4_PWR w0.381: v1(33.25,3.72) 33.25,2.85 31.17,0.77 11.54,0.77 10.81,1.5 10.8,1.5 10.79,1.51 9.18,1.51
  BOTTOM w0.203: J901.11 v1(32.18,54.46) ; J901.1 v1(32.24,56.46)
  BOTTOM w0.381: v1(50.59,4.66) 50.19,4.26 46.2,4.26 45.19,5.26 42.91,5.26 42.07,4.43 36.71,4.43 36.25,3.97 34.25,3.97 33.99,3.72 v1(33.25,3.72)
VSD2_3V3: length 150.6
  TOP w0.203: R967.1 7.14,8.67 v1(7.14,8.64)
  TOP w0.381: 34.99,5.24 41.31,5.24 41.99,4.55 41.99,3.41 44.2,1.21 64.55,1.21 67.84,4.5 67.84,14.63 64.73,17.74 64.73,27.28 65.39,27.94 66.75,27.94
  L3_INT_1 w0.203: v1(33.17,4.32) 32.55,4.32 31.42,5.44 24.09,5.44 22.76,6.76 14.97,6.76 14.2,6 8.84,6 7.24,7.6 7.24,8.54 v1(7.14,8.64)
  L3_INT_1 w0.305: v1(46.51,4.81) 47.25,4.07 63.59,4.07 67.59,8.08 67.59,25.17 67.03,25.73 67.03,27.62 v1(67.44,28.03)
  BOTTOM w0.305: v1(46.51,4.81) 45.5,5.82 42.47,5.82 41.86,5.21 35.06,5.21 34.8,4.96 R801.2
  BOTTOM w0.381: v1(33.17,4.32) 33.81,4.96 R801.2
  vias: v1(68.15,28.02) v1(68.84,28)
VSD_3V3: length 50.1
  TOP w0.203: U701.23 25.15,16.47 24.85,16.16 ; v1(7.73,8.67) 7.73,9.17 R957.1
  TOP w0.254: 24.85,16.16 24.29,15.6 24.29,15.2 24.03,14.94 23.88,14.94 C725.1
  TOP w0.305: C725.1 23.8,14.56 23.49,14.26 22.61,14.26 21.93,13.57 v1(21.7,13.57)
  L3_INT_1 w0.203: v1(31.63,5.85) 31.55,5.77 24.22,5.77 22.9,7.09 14.71,7.09 13.95,6.33 9.05,6.33 7.6,7.78 7.6,8.54 v1(7.73,8.67)
  BOTTOM w0.381: v1(21.7,13.57) 21.65,13.57 20.67,12.59 20.67,10.41 21.93,9.15 27.64,9.15 28.33,8.47 29.01,8.47 v1(31.63,5.85) ; v1(33.53,7.35) 33.53,6.81 R801.1
VSYS_5V: length 164.7
  TOP w0.203: R916.1 5.86,34.51 v1(5.86,33.92) ; R984.1 12.1,29.28 v1(12.3,29.47)
  TOP w0.254: U701.26 26.57,14.95 C1021.1 ; 27.37,20.1 U701.13 ; v1(28.76,20.89) 28.49,21.15 C1022.1 28.23,21.01 28.23,20.73
  TOP w0.305: v1(28.25,20.71) 28.23,20.73 27.61,20.73 C704.2 27.37,20.73 27.37,20.1 ; v1(25.94,14.56) 26.21,14.83 C1021.1
  TOP w0.33: C713.1 28.23,14.78 v1(28.23,14.94) 28.17,15 U701.30
  L3_INT_1 w0.203: v1(38.56,6.05) 38.84,6.05 39.27,5.62 39.27,5.34 37.95,4.02 35.54,4.02 31.76,7.8 28.35,7.8 27.69,8.47 15.42,8.47 12.07,11.82 12.07,26.68 12.66,27.26 12.66,29.12 v1(12.3,29.47) ; v1(46.56,1.81) 46.56,1.3 46.21,0.95 38.37,0.95 38.36,0.94 14.15,0.94 14.14,0.95 14.1,0.95 10.71,4.34 7.81,4.34 5.24,6.91 5.24,33.49 5.67,33.92 v1(5.86,33.92)
  BOTTOM w0.381: 24.29,17.69 24.29,19.18 R1085.1
  BOTTOM w0.508: 27.21,1.66 27.21,1.27 26.7,0.76 11.7,0.76 9.91,2.55 9.91,16.39 v1(9.15,17.15)
  vias: v1(25.38,15.15) v1(25.46,14.66) v1(25.84,15.04) v1(27.41,2.5) v1(27.82,2.17) v1(28.23,2.5) v1(29.06,13.98) v1(29.44,13.67) v1(29.8,14) v1(30.61,17.94) v1(31.07,18.3) v1(31.65,18.4) v1(32.92,18.32) v1(38,6.05) v1(38.06,7.42) v1(38.54,7.6) v1(38.54,7.09) v1(38.54,6.56) v1(44.56,3.25) v1(44.56,2.72) v1(45.14,3.28) v1(45.12,2.72) v1(45.7,3.23) v1(45.73,2.72)
WDOG_B: length 14.7
  TOP w0.091: U101.J18 56.22,39.25 v1(56.22,39.25)
  L3_INT_1 w0.114: v1(68.2,40.65) 68.2,40.63 68.08,40.51 68.08,40.49 67.86,40.26 66.18,40.26 65.49,39.57 56.54,39.57 v1(56.22,39.25)
  BOTTOM w0.112: v1(68.2,40.65) 68.2,40.52 67.93,40.24 J803.17
XTALI_24M: length 17.1
  TOP w0.081: U101.D18 56.63,42.2 v1(56.68,42.14)
  TOP w0.112: v1(61.88,48.91) 62.07,49.1 Y401.1 63.26,49.04 64.19,48.1 65.65,48.1 66,48.45 R414.1 66.38,48.45 C403.1 67.11,49.27 TP417.1
  L3_INT_1 w0.114: v1(61.88,48.91) 60.45,47.47 58.89,47.47 57.21,45.79 57.21,42.67 v1(56.68,42.14)
XTALI_32K: length 15.2
  TOP w0.081: U101.E16 v1(55.71,41.7)
  TOP w0.112: v1(61.67,50.34) 62.61,50.34 62.89,50.63 R412.1 63.87,50.63 R411.2 63.88,50.63 TP412.1
  L3_INT_1 w0.114: v1(61.67,50.34) 59.45,48.12 58.49,48.12 56.33,45.96 56.33,42.31 v1(55.71,41.7)
XTALO_24M: length 17.4
  TOP w0.081: U101.E18 v1(56.22,41.14)
  TOP w0.112: 64.86,47 63.88,47.98 62.18,47.98 v1(61.87,48.28) ; 64.86,47 64.86,47 65.56,47.7 R414.2 66.37,46.74 C404.1 ; 64.86,47 Y401.3
  L3_INT_1 w0.114: v1(61.87,48.28) 60.75,47.16 59.02,47.16 57.52,45.67 57.52,42.44 v1(56.22,41.14)
XTALO_32K: length 16.6
  TOP w0.081: U101.D16 55.7,42.2 v1(55.71,42.2)
  TOP w0.112: C402.1 62.62,53.11 62.41,52.9 QZ401.1 61.65,51.87 61.34,51.56 R413.2 61.34,50.65 v1(61.03,50.35)
  L3_INT_1 w0.114: v1(61.03,50.35) 59.14,48.46 58.48,48.46 56.06,46.03 56.06,42.55 v1(55.71,42.2)
N113524078: length 5.9
  TOP w0.112: C401.1 63.26,53.09 63.44,52.9 QZ401.2 64.15,52.41 63.19,51.45 R412.2 63.16,51.19 62.36,51.19 62.17,51 R413.1
N113540349: length 10.4
  TOP w0.254: D903.2 D904.2 26.11,55.69 26.29,55.51 26.29,54.11 25.87,53.68 R952.2 24.02,51.48 U909.11
N113540351: length 2.7
  TOP w0.112: R961.2 R953.2 21.13,54.27 U909.16
N113540485: length 3.6
  TOP w0.112: U909.5 20.32,49.72 19.84,49.25 R982.1 R960.1
N113540576: length 5.1
  TOP w0.112: U909.4 20.03,50.48 R962.1 R981.1
N113540605: length 5.9
  TOP w0.457: R1103.2 61.51,6.73
  TOP w0.508: D901.2 57.48,6.73 C914.1 61.5,6.73 U905.5
N113540646: length 4.5
  TOP w0.112: U909.3 18.52,50.98 R980.1 R963.1
N113540680: length 4.2
  TOP w0.112: R979.1 R964.1 17.78,51.48 U909.2
N113540755: length 4.4
  TOP w0.112: U909.1 18.28,51.98 R978.1 R966.1
N113540996: length 2.7
  TOP w0.305: Q901.3 28.74,59.39 D904.1
N113787187: length 3
  TOP w0.254: U902.16 5.23,42.85 3.98,44.1 R915.1
N113787601: length 2
  TOP w0.305: R912.1 5.88,37.44 U902.6
N113787940: length 2.9
  TOP w0.254: U902.1 2.99,41.44 R913.1 2.57,42.93 R914.1
N113791010: length 3.7
  TOP w0.254: U902.11 v1(9.12,40.79) 9.6,40.79 C902.1 10.74,41 R902.2
  BOTTOM w0.203: R1044.2 8.91,40.44 9.12,40.65 v1(9.12,40.79)
N113791044: length 4.2
  TOP w0.254: R903.2 10.6,41.75 C902.2 9.76,41.79 9.4,41.79 9.11,41.49 v1(9.11,41.44) U902.12
  BOTTOM w0.203: R1045.2 9.7,40.84 v1(9.11,41.44)
N113791152: length 3.5
  TOP w0.254: v1(7.52,36.45) R911.2
  TOP w0.305: v1(7.52,36.45) 7.34,36.64 C907.1 7.37,37.12 7.37,37.6 7.18,37.79 U902.8
  BOTTOM w0.203: v1(7.52,36.45) R911.2 R1042.2
N113791186: length 3.4
  TOP w0.254: R916.2 v1(6.44,36.46)
  TOP w0.305: U902.7 6.53,37.14 C907.2 6.59,36.62 v1(6.44,36.46)
  BOTTOM w0.203: R1043.2 6.44,35.85 6.44,36.46 v1(6.44,36.46)
N113791216: length 2.8
  TOP w0.254: U902.10 9.36,40.14 C908.1 10.78,39.72 R917.2
N113791250: length 3
  TOP w0.254: R918.2 10.52,38.97 C908.2 9.3,38.97 8.78,39.49 U902.9
N113798682: length 2.7
  TOP w0.254: U904.11 9.41,53.81 9.57,53.97 ; R921.2 9.64,53.9 9.57,53.97 ; 9.57,53.97 C910.1
N113798752: length 2.8
  TOP w0.254: U904.12 8.74,54.46 9,54.72 C910.2 10.37,54.72 R923.2
N113798791: length 2.5
  TOP w0.254: U904.13 7.08,55.98 7.3,56.19 7.3,56.92 C917.1 7.48,57.13 R924.2
N113798839: length 2.5
  TOP w0.254: U904.14 6.53,55.56 C917.2 6.39,57.08 R927.2
N113798887: length 2.9
  TOP w0.254: U904.8 7.12,51.48 7.12,49.85 C920.1 7.21,48.91 R929.2
N113798893: length 2.2
  TOP w0.254: R930.1 5.78,50.25 U904.6
N113798925: length 2.6
  TOP w0.254: U904.1 3.29,54.46 R933.1 2.78,56.03 R934.1
N113798968: length 2.8
  TOP w0.254: R935.2 6.47,48.91 C920.2 6.43,49.78 U904.7
N113799011: length 2.8
  TOP w0.254: U904.10 9.06,53.16 C921.1 10.51,52.66 R937.2
N113799045: length 2.9
  TOP w0.254: U904.9 8.74,52.51 9.35,51.91 C921.2 10.44,51.91 R939.2
N113816310: length 2.8
  TOP w0.254: R941.2 23.83,40.8 C924.1 22.86,40.64 U907.11
N113816380: length 2.8
  TOP w0.254: R943.2 23.72,41.55 C924.2 22.15,41.55 21.89,41.29 U907.12
N113816419: length 2.2
  TOP w0.254: U907.13 20.29,42.77 20.47,42.95 20.47,43.46 C927.1 20.51,43.53 R945.2
N113816455: length 2.3
  TOP w0.254: R947.2 19.41,43.95 19.71,43.66 C927.2 19.71,42.95 19.64,42.89 U907.14
N113816503: length 2.7
  TOP w0.254: U907.8 20.29,36.74 C932.1 20.31,35.8 R949.2
N113816509: length 2.1
  TOP w0.254: U907.6 18.99,37.51 R950.1
N113816541: length 3.2
  TOP w0.254: U907.1 15.95,41.29 R955.1 15.48,42.86 R956.1
N113816573: length 2.8
  TOP w0.254: U907.7 19.64,36.8 C932.2 19.56,35.94 R958.2
N113819379: length 2.8
  TOP w0.254: R983.2 10.92,28.27 C936.1 9.57,27.83 U911.11
N113819449: length 2.9
  TOP w0.254: R984.2 10.74,29.02 C936.2 9.43,29.02 8.9,28.48 U911.12
N113819488: length 2.6
  TOP w0.254: R987.2 8.02,31.84 7.62,31.44 C939.1 7.62,30.28 7.42,30.07 U911.13
N113819524: length 2.4
  TOP w0.254: R989.2 6.87,31.8 C939.2 6.87,30.37 6.77,30.26 U911.14
N113819572: length 2.2
  TOP w0.254: R991.2 7.48,23.64 C940.1 7.42,24.41 U911.8
N113819642: length 2.1
  TOP w0.254: R996.2 6.73,23.65 C940.2 6.77,24.38 U911.7
N113819644: length 2.8
  TOP w0.254: R994.1 3.01,30.05 R993.1 3.46,28.48 U911.1
N113819688: length 2.8
  TOP w0.254: U911.16 5.46,30.63 R995.1
N113819696: length 2.8
  TOP w0.254: U911.10 9.76,27.18 C941.1 10.85,26.94 R997.2
N113819730: length 2.8
  TOP w0.254: R1000.2 10.8,26.19 C941.2 10,26.17 9.28,26.17 8.91,26.53 U911.9
N113821648: length 2.8
  TOP w0.254: R1005.2 11.16,14.39 C945.1 10.08,14.39 10.07,14.39 U912.11
N113821718: length 3
  TOP w0.254: R1006.2 10.52,15.52 C945.2 10.1,15.09 8.49,15.09 U912.12
N113821847: length 2.4
  TOP w0.254: R1023.1 5.47,10.6 6.13,11.26 U912.6
N113821913: length 2.6
  TOP w0.254: U912.1 3.48,15.04 R1024.1 3.09,16.52 R1025.1
N113821965: length 3.1
  TOP w0.254: U912.10 9.6,13.73 C950.1 11.05,13.17 R1028.2
N113821999: length 3.1
  TOP w0.254: U912.9 9.03,13.08 9.66,12.45 10.13,12.45 C950.2 10.97,12.42 R1029.2
N114152142: length 1.1
  TOP w0.081: v1(51.74,42.26) 51.68,42.2 U101.D8
  BOTTOM w0.112: R302.2 51.8,42.2 v1(51.74,42.26)
N114616846: length 1.5
  TOP w0.381: D601.2 69.42,18.48 R605.2
N114789657: length 4.2
  TOP w0.112: U914.4 36.79,48.43 R1016.1 37.09,48.12 37.09,47.87 37.67,47.29 R1012.2 38.47,47.18 TP954.1
N114789678: length 4.2
  TOP w0.112: U914.5 36.91,49.38 R1018.1 36.92,49.49 37.24,49.82 37.24,49.93 37.67,50.35 R1013.2 38.44,50.48 TP955.1
N114814991: length 1.1
  TOP w0.081: v1(54.73,42.2) 54.73,42.2 U101.D14
  BOTTOM w0.152: v1(54.73,42.2) 54.87,42.07 R305.1
N114815134: length 1.1
  TOP w0.081: U101.D12 53.26,42.23 53.73,42.23 53.75,42.22 v1(53.79,42.22)
  BOTTOM w0.091: v1(53.79,42.22) 53.8,42.2 54.16,42.2 R303.1
N115328449: length 2.2
  TOP w0.254: U912.8 7.43,10.93 C933.1 7.68,10.68 R957.2
N115328489: length 2.2
  TOP w0.254: U912.7 6.78,11.01 C933.2 6.57,10.8 R967.2
N115328624: length 2.9
  TOP w0.254: R1022.2 23.86,39.54 C949.1 22.58,39.99 U907.10
N115328664: length 3
  TOP w0.254: R1026.2 23.66,38.79 C949.2 22.57,38.79 22.02,39.34 U907.9
N115344996: length 2.7
  TOP w0.203: U902.13 7.18,43 7.54,43.35 C948.1 7.54,44.89 R1008.2
N115345040: length 2.8
  TOP w0.203: R1020.2 6.49,44.1 C948.2 6.79,43.75 6.48,43.44 6.48,42.49 U902.14
N115345198: length 2.2
  TOP w0.254: R905.2 7.79,17.86 C905.1 7.79,16.66 7.43,16.3 U912.13
N115345238: length 2.2
  TOP w0.254: U912.14 6.78,16.89 C905.2 7.04,17.89 R909.2
N115885549: length 3
  TOP w0.112: 31.25,50.03 30.71,50.57 R1011.2 ; 31.25,50.03 31.55,50.33 U914.1 ; 31.25,50.03 R1010.1
N115885630: length 4.5
  TOP w0.112: R1010.2 31.25,48 R1015.1 31.88,48.43 U914.3 32.75,47.45 TP953.1
N115909883: length 2.7
  TOP w0.112: 21.85,48.14 21.63,48.35 U909.6 ; 21.85,48.14 R969.1 ; 21.85,48.14 R977.2
N115909890: length 3
  TOP w0.112: U909.7 22.13,48.77 R976.2 22.78,48.13 R970.1
N115909893: length 4.4
  TOP w0.112: R975.2 24.9,48.15 R972.1 24.88,49.03 24.19,49.72 U909.8
N115909896: length 3.5
  TOP w0.112: R1037.2 25.89,50.29 R1034.1 25.7,50.48 U909.9
N115909899: length 3.6
  TOP w0.112: U909.10 25.47,50.98 R1036.2 R1035.1
N115939435: length 1.4
  TOP w0.203: C951.1 16.36,17.56 15.97,17.16 U903.1
N115957390: length 8.6
  TOP w0.203: R922.1 13.34,19.31 v1(13.34,17.79) ; v1(13.97,13.6) 13.98,13.6 13.98,13.81 14.47,14.3 U903.7
  BOTTOM w0.203: v1(13.97,13.6) 14.99,14.62 14.99,16.14 v1(13.34,17.79)
N115991020: length 1.1
  TOP w0.254: v1(43.43,16.73) U906.1
  BOTTOM w0.305: v1(43.43,16.73) C952.1
N115994234: length 1.8
  TOP w0.152: R938.1 45.34,20.47 44.93,20.07 U906.7
N115999748: length 1.4
  TOP w0.203: C953.1 17.85,26.33 U908.1
N116003893: length 7.1
  TOP w0.203: v1(19.01,26.31) 19.98,25.34 R951.1 ; v1(19.07,30.63) 19.35,30.35 U908.7
  L3_INT_1 w0.203: v1(19.07,30.63) 18.75,30.32 18.75,26.58 v1(19.01,26.31)
N116014384: length 1.2
  TOP w0.203: U910.1 36.52,26.72 36.28,26.48 C954.1
N116018297: length 9.3
  TOP w0.203: R985.1 39.47,24.71 40.95,26.19 40.95,29.11 40.5,29.56 38.3,29.56 38.02,29.28 U910.7
N116041401: length 2.2
  TOP w0.203: U901.5 47.17,9.74 47.17,11 R908.2
N116046959: length 5.1
  TOP w0.203: U901.6 45.98,9.38 v1(46.24,9.65)
  BOTTOM w0.203: R907.1 48.06,7.83 v1(46.24,9.65)
N116083878: length 2.8
  TOP w0.254: R936.1 5.13,56.59 U904.16
N116107496: length 2.8
  TOP w0.254: U907.16 18.34,42.49 16.79,44.05 R959.1
N116113800: length 2.3
  TOP w0.254: U911.5 5.46,24.85 4.58,23.96 R990.1
N116121400: length 2.2
  TOP w0.254: U911.6 6.11,24.56 5.52,23.96 R992.1
N116137130: length 2.4
  TOP w0.254: R1027.1 4.61,17.65 5.48,16.78 U912.16
N116434057: length 1.7
  TOP w0.203: C706.2 26.6,20.8 26.6,20.51 26.97,20.13 U701.14
N116434617: length 4.8
  TOP w0.112: U701.25 26.01,15.7 25.25,15.7 24.87,15.32 24.87,14.61 25.46,14.03 25.46,13.14 v1(25.13,12.81)
  BOTTOM w0.112: v1(25.13,12.81) R707.2
N116434898: length 2.9
  TOP w0.203: 27.77,14.46 U701.29
  TOP w0.381: L704.1 28,13.18 28,13.57 27.77,13.79 27.77,14.46
N116434901: length 3
  TOP w0.254: 26.97,14.69 U701.27
  TOP w0.381: 26.97,14.69 26.97,14.02 26.65,13.7 26.65,13.2 L706.1
N116471687: length 3.3
  TOP w0.112: U701.18 25.28,18.47 v1(24.97,18.78)
  BOTTOM w0.112: R1059.1 23.75,20.71 24.97,19.49 v1(24.97,18.78)
N116471690: length 1.9
  TOP w0.112: U701.12 27.77,19.92 27.92,20.07 v1(27.92,20.1)
  BOTTOM w0.112: v1(27.92,20.1) 28.67,20.1 R1083.1
N116476004: length 5
  TOP w0.203: 30.03,18.07 U701.6
  TOP w0.254: 30.03,18.07 30.76,18.8 31.37,18.8 31.87,19.3 C1013.2 31.73,19.5 v1(31.73,20.05)
  BOTTOM w0.203: R1065.2 R1066.2
  BOTTOM w0.254: v1(31.73,20.05) 31.73,19.57 31.95,19.34 R1065.2
N116660464: length 2.5
  TOP w0.112: U701.10 28.57,19.76 29.75,20.94 R714.1
N116660470: length 2.6
  TOP w0.112: U701.9 28.97,19.8 30.31,21.14 R715.1
N116675602: length 13.1
  TOP w0.081: U101.D4 49.56,42.2 v1(49.6,42.25)
  TOP w0.112: TP202.1 42.22,47.91 v1(42.42,47.71)
  BOTTOM w0.081: v1(49.6,42.25) 49.45,42.25 49.25,42.44 49.25,43.33 49.26,43.33 49.26,44.62
  BOTTOM w0.112: 49.26,44.62 49.26,46.18 47.74,47.71 v1(42.42,47.71)
N116676339: length 5.9
  TOP w0.081: 55.75,23.11 56.26,22.6 56.26,21.66 56.26,21.66 56.26,21.33 56.5,21.08 56.5,20.86 56.51,20.85 U501.K5
  TOP w0.112: 55.75,23.11 55.04,23.81 TP504.1
